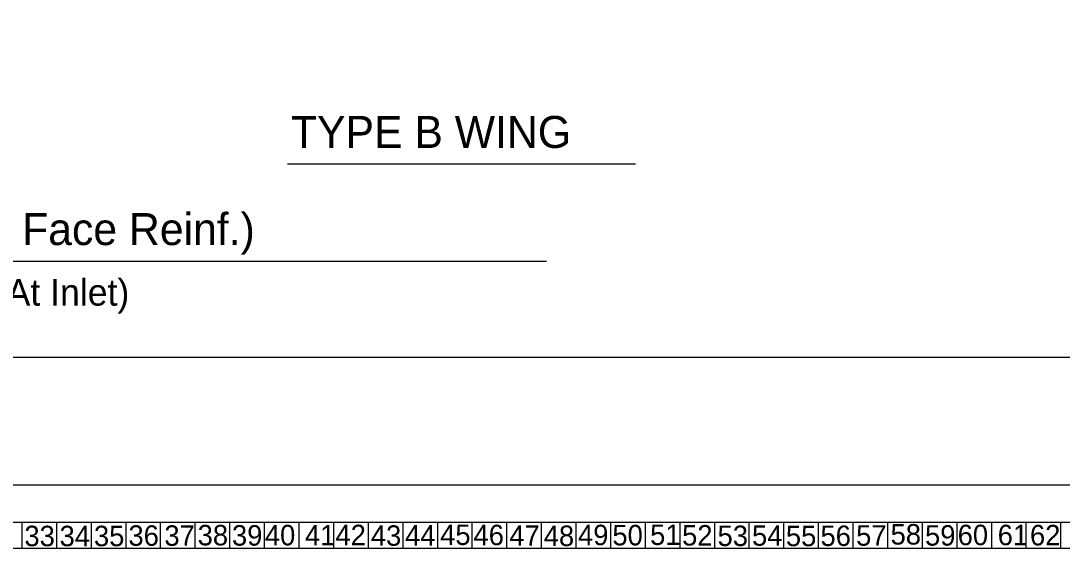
# Model space of a CAD drawing. Extents: x -0.08 to 2.83, y -0.03 to 1.92.
# Drawn here: x 0.646 to 1.156, y -0.031 to 0.227 of the extents above; entities that cross this region are included whole.
import ezdxf

# ---------------------------------------------------------------- set-up
doc = ezdxf.new("R2010")
doc.units = 0
for name, color, linetype in [('33', 7, 'Continuous'), ('34', 7, 'Continuous'), ('35', 7, 'Continuous'), ('36', 7, 'Continuous'), ('37', 7, 'Continuous'), ('38', 7, 'Continuous'), ('39', 7, 'Continuous'), ('40', 7, 'Continuous'), ('41', 7, 'Continuous'), ('42', 7, 'Continuous'), ('43', 7, 'Continuous'), ('44', 7, 'Continuous'), ('45', 7, 'Continuous'), ('46', 7, 'Continuous'), ('47', 7, 'Continuous'), ('48', 7, 'Continuous'), ('49', 7, 'Continuous'), ('50', 7, 'Continuous'), ('51', 7, 'Continuous'), ('52', 7, 'Continuous'), ('53', 7, 'Continuous'), ('54', 7, 'Continuous'), ('55', 7, 'Continuous'), ('56', 7, 'Continuous'), ('57', 7, 'Continuous'), ('58', 7, 'Continuous'), ('59', 7, 'Continuous'), ('60', 7, 'Continuous'), ('61', 7, 'Continuous'), ('62', 7, 'Continuous'), ('63', 7, 'Continuous')]:
    doc.layers.add(name, color=color, linetype=linetype)

msp = doc.modelspace()

# ---------------------------------------------------------------- linework, layer by layer
at = {"layer": '57'}
for p, q in [((0.77679, 0.15708), (0.94686, 0.15708)), ((0.45655, 0.10961), (0.90333, 0.10961))]:
    msp.add_line(p, q, dxfattribs=at)
at = {"layer": '62'}
for p, q in [((0.10494, -0.01804), (1.17174, -0.01804)), ((0.64681, -0.01804), (0.64681, -0.03074)), ((0.66374, -0.01804), (0.66374, -0.03074)), ((0.68068, -0.01804), (0.68068, -0.03074)), ((0.69761, -0.01804), (0.69761, -0.03074)), ((0.71454, -0.01804), (0.71454, -0.03074)), ((0.73147, -0.01804), (0.73147, -0.03074)), ((0.74841, -0.01804), (0.74841, -0.03074)), ((0.76534, -0.01804), (0.76534, -0.03074)), ((0.78228, -0.01804), (0.78228, -0.03074)), ((0.79921, -0.01804), (0.79921, -0.03074)), ((0.81614, -0.01804), (0.81614, -0.03074)), ((0.83308, -0.01804), (0.83308, -0.03074)), ((0.85001, -0.01804), (0.85001, -0.03074)), ((0.86694, -0.01804), (0.86694, -0.03074)), ((0.88388, -0.01804), (0.88388, -0.03074)), ((0.90081, -0.01804), (0.90081, -0.03074)), ((0.91774, -0.01804), (0.91774, -0.03074)), ((0.93468, -0.01804), (0.93468, -0.03074)), ((0.95161, -0.01804), (0.95161, -0.03074)), ((0.96854, -0.01804), (0.96854, -0.03074)), ((0.98548, -0.01804), (0.98548, -0.03074)), ((1.00241, -0.01804), (1.00241, -0.03074)), ((1.01934, -0.01804), (1.01934, -0.03074)), ((1.03628, -0.01804), (1.03628, -0.03074)), ((1.05321, -0.01804), (1.05321, -0.03074)), ((1.07014, -0.01804), (1.07014, -0.03074)), ((1.08708, -0.01804), (1.08708, -0.03074)), ((1.10401, -0.01804), (1.10401, -0.03074)), ((1.12094, -0.01804), (1.12094, -0.03074)), ((1.13787, -0.01804), (1.13787, -0.03074)), ((1.15481, -0.01804), (1.15481, -0.03074)), ((0.10494, -0.03074), (1.17174, -0.03074))]:
    msp.add_line(p, q, dxfattribs=at)
at = {"layer": '63'}
msp.add_line((2.83333, 0), (0, 0), dxfattribs=at)
msp.add_lwpolyline([(0.16668, 0.06244), (0.16668, 1.77077), (2.72918, 1.77077), (2.72918, 0.10411), (2.56251, 0.10411), (2.56251, 0.14578), (2.07387, 0.14578), (2.07387, 0.06244)], close=True, dxfattribs=at)

# ---------------------------------------------------------------- texts
at = {"layer": '33'}
msp.add_text('33', height=0.01, rotation=360, dxfattribs=at).set_placement((0.64808, -0.02978))
at = {"layer": '34'}
msp.add_text('34', height=0.01, rotation=360, dxfattribs=at).set_placement((0.66527, -0.02978))
at = {"layer": '35'}
msp.add_text('35', height=0.01, rotation=360, dxfattribs=at).set_placement((0.68209, -0.02978))
at = {"layer": '36'}
msp.add_text('36', height=0.01, rotation=360, dxfattribs=at).set_placement((0.69895, -0.02958))
at = {"layer": '37'}
msp.add_text('37', height=0.01, rotation=360, dxfattribs=at).set_placement((0.71654, -0.02958))
at = {"layer": '38'}
msp.add_text('38', height=0.01, rotation=360, dxfattribs=at).set_placement((0.73281, -0.02938))
at = {"layer": '39'}
msp.add_text('39', height=0.01, rotation=360, dxfattribs=at).set_placement((0.74958, -0.0295))
at = {"layer": '40'}
msp.add_text('40', height=0.01, rotation=360, dxfattribs=at).set_placement((0.76566, -0.02938))
at = {"layer": '41'}
msp.add_text('41', height=0.01, rotation=360, dxfattribs=at).set_placement((0.78528, -0.02938))
at = {"layer": '42'}
msp.add_text('42', height=0.01, rotation=360, dxfattribs=at).set_placement((0.8002, -0.0293))
at = {"layer": '43'}
msp.add_text('43', height=0.01, rotation=360, dxfattribs=at).set_placement((0.8175, -0.02958))
at = {"layer": '44'}
msp.add_text('44', height=0.01, rotation=360, dxfattribs=at).set_placement((0.83425, -0.02949))
at = {"layer": '45'}
msp.add_text('45', height=0.01, rotation=360, dxfattribs=at).set_placement((0.85139, -0.02918))
at = {"layer": '46'}
msp.add_text('46', height=0.01, rotation=360, dxfattribs=at).set_placement((0.8677, -0.02929))
at = {"layer": '47'}
msp.add_text('47', height=0.01, rotation=360, dxfattribs=at).set_placement((0.8852, -0.02958))
at = {"layer": '48'}
msp.add_text('48', height=0.01, rotation=360, dxfattribs=at).set_placement((0.90205, -0.02969))
at = {"layer": '49'}
msp.add_text('49', height=0.01, rotation=360, dxfattribs=at).set_placement((0.91882, -0.02929))
at = {"layer": '50'}
msp.add_text('50', height=0.01, rotation=360, dxfattribs=at).set_placement((0.93563, -0.02938))
at = {"layer": '51'}
msp.add_text('51', height=0.01, rotation=360, dxfattribs=at).set_placement((0.95407, -0.02918))
at = {"layer": '52'}
msp.add_text('52', height=0.01, rotation=360, dxfattribs=at).set_placement((0.96972, -0.02946))
at = {"layer": '53'}
msp.add_text('53', height=0.01, rotation=360, dxfattribs=at).set_placement((0.98705, -0.0297))
at = {"layer": '54'}
msp.add_text('54', height=0.01, rotation=360, dxfattribs=at).set_placement((1.0039, -0.02958))
at = {"layer": '55'}
msp.add_text('55', height=0.01, rotation=360, dxfattribs=at).set_placement((1.02047, -0.02978))
at = {"layer": '56'}
msp.add_text('56', height=0.01, rotation=360, dxfattribs=at).set_placement((1.03739, -0.02967))
at = {"layer": '57'}
for s, height, p in [('TYPE B WING', 0.015625, (0.77841, 0.16489)), ('ELEVATION (Front Face Reinf.)', 0.015625, (0.46235, 0.11742)), ('(Shown At Inlet)', 0.0130208, (0.5755, 0.0878))]:
    msp.add_text(s, height=height, dxfattribs=at).set_placement(p)
msp.add_text('57', height=0.01, rotation=360, dxfattribs=at).set_placement((1.05482, -0.02955))
at = {"layer": '58'}
msp.add_text('58', height=0.01, rotation=360, dxfattribs=at).set_placement((1.07167, -0.02898))
at = {"layer": '59'}
msp.add_text('59', height=0.01, rotation=360, dxfattribs=at).set_placement((1.08852, -0.0295))
at = {"layer": '60'}
msp.add_text('60', height=0.01, rotation=360, dxfattribs=at).set_placement((1.10448, -0.02929))
at = {"layer": '61'}
msp.add_text('61', height=0.01, rotation=360, dxfattribs=at).set_placement((1.12406, -0.02929))
at = {"layer": '62'}
msp.add_text('62', height=0.01, rotation=360, dxfattribs=at).set_placement((1.13984, -0.02938))

doc.saveas('drawing.dxf')
